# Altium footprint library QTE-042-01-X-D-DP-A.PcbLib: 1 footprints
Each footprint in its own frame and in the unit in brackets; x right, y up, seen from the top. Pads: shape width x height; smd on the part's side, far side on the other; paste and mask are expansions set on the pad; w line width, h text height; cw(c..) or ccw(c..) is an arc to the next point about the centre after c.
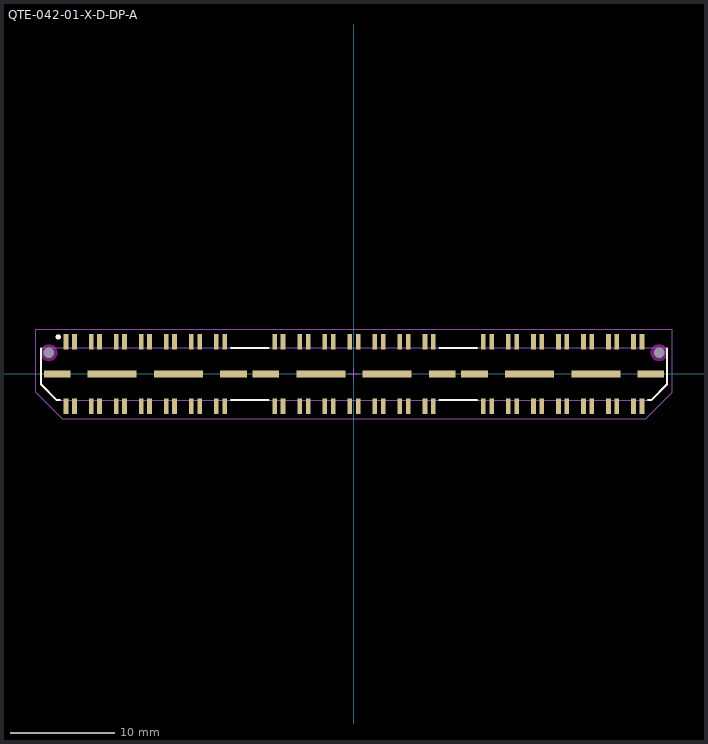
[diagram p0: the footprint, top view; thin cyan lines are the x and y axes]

## QTE-042-01-X-D-DP-A [mm] "0.80mm pitch, 84 pin, high speed terminal strip; differential"
height 4.27
pads (98):
  rect 0.45x1.45 smd mask+0: 1(-27.6,3.09) 2(-27.6,-3.09) 3(-26.8,3.09) 4(-26.8,-3.09) 5(-25.2,3.09) 6(-25.2,-3.09) 7(-24.4,3.09) 8(-24.4,-3.09) 9(-22.8,3.09) 10(-22.8,-3.09) 11(-22,3.09) 12(-22,-3.09) 13(-20.4,3.09) 14(-20.4,-3.09) 15(-19.6,3.09) 16(-19.6,-3.09) 17(-18,3.09) 18(-18,-3.09) 19(-17.2,3.09) 20(-17.2,-3.09) 21(-15.6,3.09) 22(-15.6,-3.09) 23(-14.8,3.09) 24(-14.8,-3.09) 25(-13.2,3.09) 26(-13.2,-3.09) 27(-12.4,3.09) 28(-12.4,-3.09) 29(-7.6,3.09) 30(-7.6,-3.09) 31(-6.8,3.09) 32(-6.8,-3.09) 33(-5.2,3.09) 34(-5.2,-3.09) 35(-4.4,3.09) 36(-4.4,-3.09) 37(-2.8,3.09) 38(-2.8,-3.09) 39(-2,3.09) 40(-2,-3.09) 41(-0.4,3.09) 42(-0.4,-3.09) 43(0.4,3.09) 44(0.4,-3.09) 45(2,3.09) 46(2,-3.09) 47(2.8,3.09) 48(2.8,-3.09) 49(4.4,3.09) 50(4.4,-3.09) 51(5.2,3.09) 52(5.2,-3.09) 53(6.8,3.09) 54(6.8,-3.09) 55(7.6,3.09) 56(7.6,-3.09) 57(12.4,3.09) 58(12.4,-3.09) 59(13.2,3.09) 60(13.2,-3.09) 61(14.8,3.09) 62(14.8,-3.09) 63(15.6,3.09) 64(15.6,-3.09) 65(17.2,3.09) 66(17.2,-3.09) 67(18,3.09) 68(18,-3.09) 69(19.6,3.09) 70(19.6,-3.09) 71(20.4,3.09) 72(20.4,-3.09) 73(22,3.09) 74(22,-3.09) 75(22.8,3.09) 76(22.8,-3.09) 77(24.4,3.09) 78(24.4,-3.09) 79(25.2,3.09) 80(25.2,-3.09) 81(26.8,3.09) 82(26.8,-3.09) 83(27.6,3.09) 84(27.6,-3.09)
  rect 2.55x0.65 smd mask+0: 85(-28.445,0) 88(-11.555,0) 89(-8.445,0) 92(8.445,0) 93(11.555,0) 96(28.445,0)
  rect 4.7x0.65 smd mask+0: 86(-23.175,0) 87(-16.825,0) 90(-3.175,0) 91(3.175,0) 94(16.825,0) 95(23.175,0)
  round 0.5 hole 1 unplated mask+0: 97(-29.24,2.04) 98(29.24,2.04)
Top Overlay:
  circle w0.25: c-28.35,3.55 r0.125
  lines w0.2: -30,2.45 -30,-1 -28.5,-2.5 -28.2,-2.5 ; -11.8,-2.5 -8.2,-2.5 ; -11.8,2.5 -8.2,2.5 ; 8.2,-2.5 11.8,-2.5 ; 8.2,2.5 11.8,2.5 ; 28.2,-2.5 28.5,-2.5 30,-1 30,2.45
Keep-Out Layer:
  pour cut-out: -28.433,2.04 -28.461,2.249 -28.541,2.443 -28.669,2.611 -28.837,2.739 -29.031,2.819 -29.24,2.847 -29.449,2.819 -29.643,2.739 -29.811,2.611 -29.939,2.443 -30.019,2.249 -30.047,2.04 -30.019,1.831 -29.939,1.637 -29.811,1.469 -29.643,1.341 -29.449,1.261 -29.24,1.233 -29.031,1.261 -28.837,1.341 -28.669,1.469 -28.541,1.637 -28.461,1.831
  pour cut-out: 30.047,2.04 30.019,2.249 29.939,2.443 29.811,2.611 29.643,2.739 29.449,2.819 29.24,2.847 29.031,2.819 28.837,2.739 28.669,2.611 28.541,2.443 28.461,2.249 28.433,2.04 28.461,1.831 28.541,1.637 28.669,1.469 28.837,1.341 29.031,1.261 29.24,1.233 29.449,1.261 29.643,1.341 29.811,1.469 29.939,1.637 30.019,1.831
Mechanical 12:
  lines w0.001: -30,-1 -28.5,-2.5 28.5,-2.5 30,-1 30,2.5 -30,2.5 -30,-1
Mechanical 13:
  lines w0.1: -30,-1 -28.5,-2.5 28.5,-2.5 30,-1 30,2.5 -30,2.5 -30,-1
  text ".Designator" at 0.254,0.254 h1.52
Mechanical 15:
  lines w0.05: -0.5,0 0.5,0 ; 0,-0.5 0,0.5 ; -30.5,-1.75 -27.95,-4.3 27.95,-4.3 30.5,-1.75 30.5,4.3 -30.5,4.3 -30.5,-1.75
